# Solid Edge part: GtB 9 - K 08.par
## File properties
Author: Carsten
Template: Normal.par
Last saved by: Carsten
Revision: 5
Application: Solid Edge
Genauigkeit: 0,99
Teilflächenrmatvorlage: Model Default
Coef. of Thermal Exp: 0.0
Thermal Conductivity: 0.0
Specific Heat: 0.0
Modulus of Elasticity: 0.0
Poission's Ratio: 0.0
Yield Stress: 0.0
Ultimate Stress: 0.0
Elongation: 0.0
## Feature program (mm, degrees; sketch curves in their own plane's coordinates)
sketch for "unnamed Protrusion 1" plane through (0, 0, 0) normal (0, 0, 1) x-axis (1, 0, 0)
  line (-23.9455, 22.8253) -> (46.0545, 22.8253)
  line (46.0545, 22.8253) -> (46.0545, -42.1747)
  line (46.0545, -42.1747) -> (-23.9455, -42.1747)
  line (-23.9455, -42.1747) -> (-23.9455, 22.8253)
extrude "unnamed Protrusion 1" add finite 85 along +normal
sketch for "Ausschnitt_1" #1 plane through (11.0545, -42.1747, 42.5) normal (0, -1, 0) x-axis (1, 0, 0)
  line (20, 42.5) -> (20, -17.5)
  line (20, -17.5) -> (30, -17.5)
  line (30, -17.5) -> (30, 42.5)
  line (30, 42.5) -> (20, 42.5)
sketch for "Ausschnitt_1" #2 plane through (11.0545, -42.1747, 42.5) normal (0, -1, 0) x-axis (1, 0, 0)
  line (-30, 42.5) -> (-30, -17.5)
  line (-30, -17.5) -> (-20, -17.5)
  line (-20, -17.5) -> (-20, 42.5)
  line (-20, 42.5) -> (-30, 42.5)
  dimension (linear) = 30
  dimension (linear) = 30
  dimension (linear) = 30
  dimension (linear) = 20
extrude "Ausschnitt_1" cut finite 104.775 along -normal
sketch for "Ausschnitt_3" plane through (11.0545, -9.6747, 85) normal (0, 0, 1) x-axis (0, 1, 0)
  line (27.5, 10) -> (27.5, -10)
  line (27.5, -10) -> (12.5, -10)
  line (12.5, -10) -> (12.5, 10)
  line (12.5, 10) -> (27.5, 10)
  dimension (linear) = 27.5
  dimension (linear) = 27.5
extrude "Ausschnitt_3" cut finite 136.525 along -normal
sketch for "Ausschnitt_4" plane through (46.0545, -9.6747, 42.5) normal (1, 0, 0) x-axis (0, 1, 0)
  line (-32.5, -42.5) -> (-32.5, -27.5)
  line (-32.5, -27.5) -> (-2.5, -27.5)
  line (-2.5, -27.5) -> (-2.5, -42.5)
  line (-2.5, -42.5) -> (-32.5, -42.5)
extrude "Ausschnitt_4" cut finite 92.075 along -normal
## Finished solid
Body 1: solid body, 20 faces, 54 edges, 36 vertices.
  Faces by surface: plane 20
  Edges by curve: line 54
Bounding box of the edges (mm): 70.000 x 65.000 x 85.000, from (-23.9455, -42.1747, 0) to (46.0545, 22.8253, 85).
Planar faces by outward normal: +x 4, +y 2, +z 5, -x 4, -y 3, -z 2
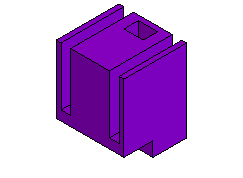
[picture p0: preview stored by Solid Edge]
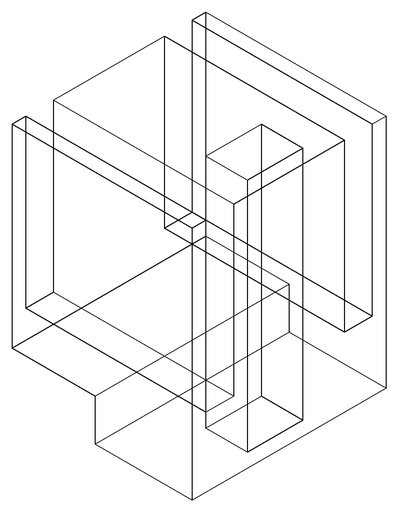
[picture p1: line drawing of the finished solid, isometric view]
